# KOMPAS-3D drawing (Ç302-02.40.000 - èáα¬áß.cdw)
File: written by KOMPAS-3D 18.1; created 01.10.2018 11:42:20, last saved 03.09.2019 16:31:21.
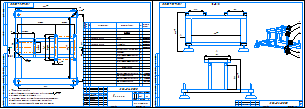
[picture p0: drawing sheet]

Sheets 1-2: A3, landscape

Document properties: Автор: Милов; Полное имя файла: \\192.168.87.28\Konstructor_doc\Мембранные насосы\Мембранный электропривод\А302-00.00.000 - ASTRA-302 (МЭ200)\3Д ПВХ\А302-01.40.000 - Каркас.a3d; Масса: 4.3918; Форматы листов документа: 2xA3

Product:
- Part/product: (unnamed)
  - Component: Виброопора РСА PCA-60 M10  | pos. 3  | Раздел спецификации: Детали
  - Component: Опора  | designation А302-02.40.001  | pos. 1  | Раздел спецификации: Детали; Форматы листов документа: А4; Примечание: Труба профильная 40х20х2 / Ст3 ГОСТ 380-2005
  - Component: Подставка  | designation А302-02.40.002  | pos. 2  | Раздел спецификации: Детали; Форматы листов документа: А4; Примечание: Труба профильная 40х20х2 / Ст3 ГОСТ 380-2005
  - Component: Труба профильная 20х20х2 / Ст3 ГОСТ 380-1005  | pos. 6  | Раздел спецификации: Материалы; Примечание: м с учётом / деталей
  - Component: Труба профильная 40х20х2 / Ст3 ГОСТ 380-1005  | pos. 7  | Раздел спецификации: Материалы; Примечание: м с учётом / деталей
  - Component: Заглушка  / для профильной трубы 40х20  | pos. 4  | Раздел спецификации: Детали
  - Component: Заглушка / для профильной трубы 20х20  | pos. 5  | Раздел спецификации: Детали

Title block, sheet 1: Наименование: Каркас; designation: А302-02.40.000; Масса: 4,39; scale: 1:1; sheet number: 1; Количество листов документа: 2; organisation: ЗАО «Астерион»; Форматы листов документа: A3; stored path: \\192.168.87.28\Konstructor_doc\Мембранные насосы\Мембранный электропривод\А302-00.00.000 - ASTRA-302 (МЭ200)\3Д ПВХ\А302-01.40.000 - Каркас.cdw; Разработал: Лифлянд; Проверил: Борисенко; Т. контр.: Лучихин; Утвердил: Григорьева
Title block, sheet 2: sheet number: 2

Views: Вид 1, Спереди, Разрез А-А, Вид по стрелке 3, Вид 4, Разрез Б-Б, Вид по стрелке А, Вид:1
Referenced files in D:\Мембранные насосы\Мембранный электропривод\А302-00.00.000 - ASTRA-302 (МЭ200)\3Д ПВХ\: А302-01.40.000 - Каркас.a3d, А302-02.40.002 - Подставка 1.m3d, А302-02.40.003 - Подставка 2.m3d, Виброопора PCA-60 M10.m3d
Referenced files in D:\Мембранные насосы\Мембранный электропривод\А302-00.00.000 - ASTRA-302 (МЭ200)\3Д ПВХ\Отработка\: Труба профильная 25х25х1,5.m3d, Труба профильная 25х25х1,5-1.m3d
Referenced files in \\192.168.87.28\Konstructor_doc\Мембранные насосы\Мембранный электропривод\А302-00.00.000 - ASTRA-302 (МЭ200)\3Д ПВХ\Отработка\: Труба профильная 25х25х1,5.m3d, Труба профильная 25х25х1,5-1.m3d, А302-01.40.002-01 - Стяжка.m3d, Труба профильная 25х25х1,5-2.m3d
Referenced files in \\192.168.87.28\Konstructor_doc\Мембранные насосы\Мембранный электропривод\А302-00.00.000 - ASTRA-302 (МЭ200)\3Д ПВХ\: А302-01.40.001 - Опора.cdw, А302-01.40.002 - Стяжка.cdw
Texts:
  Сталь
  ГОСТ
  м с учетом деталей
  Опора
  Стяжка
  Заглушка квадратная черная 20х20 мм
  арт. 20-20 СЧС
  Заглушка
  квадратная
  черная
  арт
  СЧС
  3D_Doc-graphic.lyt,1.000000-4294967295-279442559910
  Подставка 1
  м с учетом
  деталей
  м с учетом  / деталей
  Подставка 2
  Труба профильная 40х20х2
  Ст3 ГОСТ 380-2005
  Труба профильная 40х20х2 / Ст3 ГОСТ 380-2005
  Подставка
  Труба профильная 20х20х2
  Ст3 ГОСТ 380-1005
  Труба
  профильная
  м с учётом
  м с учётом / деталей
  Виброопора РСА PCA-60 M10
  для профильной трубы 40х20
  Заглушка  / для профильной трубы 40х20
  для профильной трубы 20х20
  Заглушка / для профильной трубы 20х20
  Труба профильная 20х20х1,5 / Ст3 ГОСТ 380-2005
  Виброопора PCA-60 M10
Dimensions and other numbers on the sheet: 10; 120±0,2; 266±0,3; 134±0,2; 70±0,2; 160±0,2; 130; 180; 8 отв.; 20; 11; 4 отв.; 380; 460; 420; 340; 100; 114; 267; 166; 226; 1; 2; 3; 4; 5; 4,5; 38; 6; 1,5; 7; 2,2; 12; 1:1; 4,39

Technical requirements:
  *Размеры для справок.
  Шероховатость дорабатываемых поверхностей  Ra 6,3 .
  Профили сварить по контуру  .
  Покрытие: Эмаль порошковая эпоксидно-полиэфирная,
  цвет RAL5005, шагрень (допускается глянцевая).
  Общие допуски ГОСТ 30893.2-mK (H14, h14,  t2/2).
